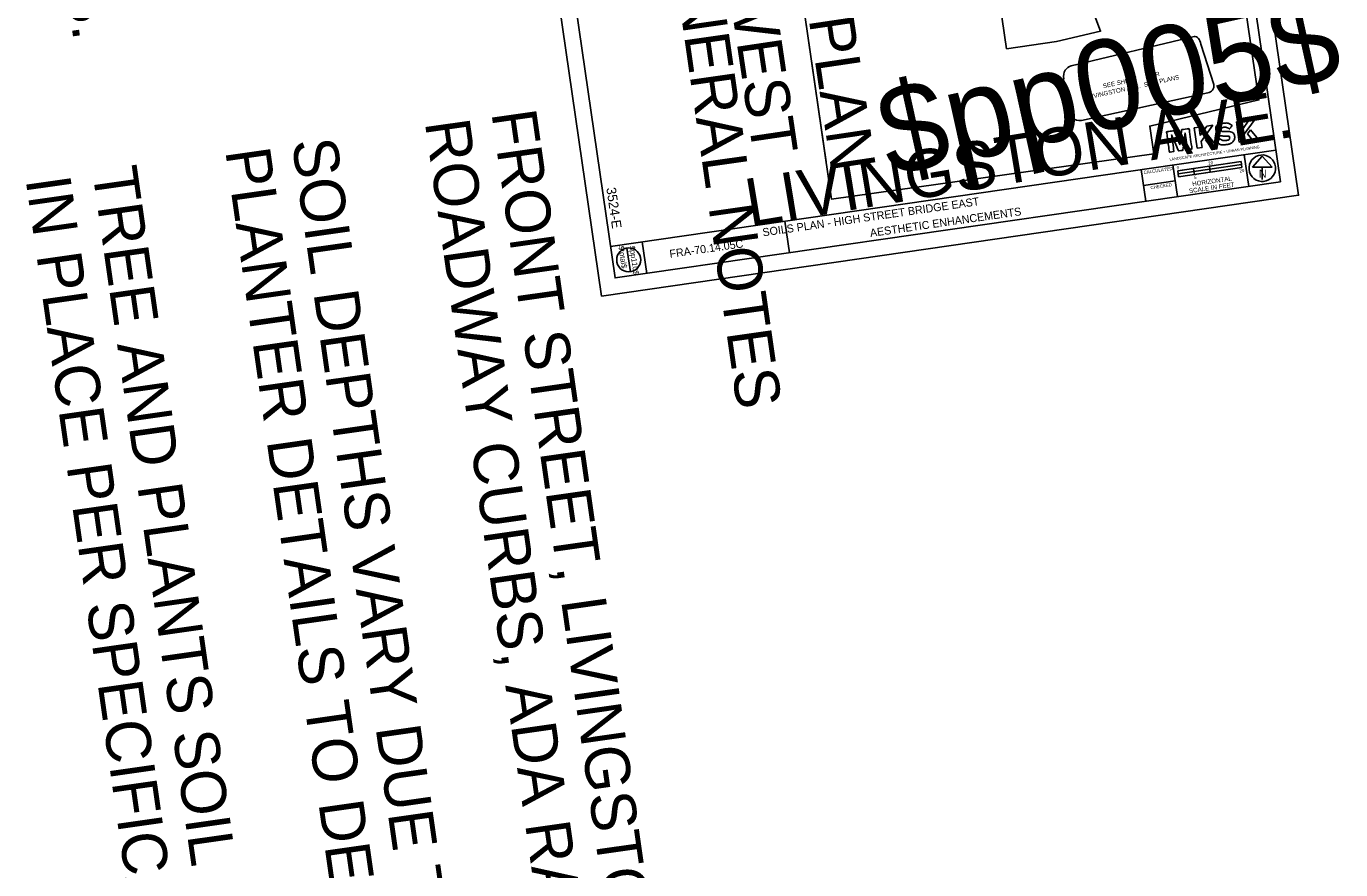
# Model space of a CAD drawing. Extents: x 1828401 to 1868248, y 433751 to 711935.
# Drawn here: x 1828401.1 to 1828811.8, y 711367.9 to 711631.6 of the extents above; entities that cross this region are included whole.
import ezdxf

# ---------------------------------------------------------------- set-up
doc = ezdxf.new("R2010")
doc.units = 0
for name, color, linetype in [('SC_Scratch1', 7, 'Continuous'), ('SC_Scratch2', 7, 'Continuous'), ('SH_Border', 7, 'Continuous'), ('SH_Cut_Line', 7, 'Continuous'), ('SH_Data', 7, 'Continuous'), ('SH_Text', 7, 'Continuous'), ('VG_P_Cells', 7, 'Continuous'), ('VG_P_Text', 7, 'Continuous')]:
    doc.layers.add(name, color=color, linetype=linetype)

# ---------------------------------------------------------------- blocks, each defined once
blk = doc.blocks.new('NARROW')
at = {"layer": 'SH_Data'}
for p, q in [((0, 0.374), (-0.308, 0.033)), ((-0.308, 0.033), (0.308, 0.033)), ((0.308, 0.033), (0, 0.374)), ((0, 0.033), (0, -0.354))]:
    blk.add_line(p, q, dxfattribs=at)
blk.add_arc((0, 0), 0.415, 129.7798, 129.7633, dxfattribs=at)
blk.add_text('N', height=0.25, rotation=360, dxfattribs=at).set_placement((-0.104, -0.291))

msp = doc.modelspace()

# ---------------------------------------------------------------- linework, layer by layer
at = {"layer": 'SC_Scratch1'}
msp.add_lwpolyline([(1828745.05, 711890.51), (1828786.22, 711608.59), (1828752.09, 711600.43), (1828753.34, 711591.74), (1828652.71, 711577.53), (1828610.22, 711870.99)], close=True, dxfattribs=at)
at = {"layer": 'SC_Scratch2'}
msp.add_lwpolyline([(1828707.37, 711624.58), (1828722.97, 711626.84), (1828736.77, 711630.05), (1828734.37, 711636.49), (1828732.45, 711641.74), (1828730.87, 711646.15), (1828729.12, 711651.11), (1828728.63, 711652.53), (1828703.84, 711648.94)], close=True, dxfattribs=at)
at = {"layer": 'SH_Border'}
for p, q in [((1828583.65, 711562.81), (1828791.49, 711592.9)), ((1828759.32, 711588.25), (1828760.76, 711578.35)), ((1828781.59, 711591.47), (1828783.02, 711581.57)), ((1828749.43, 711586.81), (1828750.86, 711576.92)), ((1828760.04, 711583.3), (1828750.14, 711581.86)), ((1828638.09, 711570.69), (1828639.52, 711560.8)), ((1828593.55, 711564.24), (1828594.98, 711554.35))]:
    msp.add_line(p, q, dxfattribs=at)
msp.add_lwpolyline([(1828747.79, 711894.75), (1828792.92, 711583.01), (1828585.09, 711552.92), (1828539.95, 711864.66)], close=True, dxfattribs=at)
at = {"layer": 'SH_Cut_Line'}
msp.add_lwpolyline([(1828532.14, 711883.74), (1828580.86, 711547.25), (1828798.59, 711578.77), (1828749.87, 711915.26)], close=True, dxfattribs=at)
at = {"layer": 'SH_Data'}
for p, q in [((1828760.85, 711586.44), (1828780.64, 711589.31)), ((1828770.74, 711587.88), (1828780.64, 711589.31)), ((1828780.78, 711588.38), (1828770.88, 711586.95)), ((1828780.91, 711587.45), (1828780.64, 711589.31)), ((1828780.64, 711589.31), (1828780.77, 711588.39)), ((1828780.77, 711588.39), (1828780.78, 711588.38)), ((1828765.8, 711587.16), (1828760.85, 711586.44)), ((1828761.12, 711584.59), (1828760.85, 711586.44)), ((1828760.85, 711586.44), (1828760.98, 711585.52)), ((1828760.98, 711585.52), (1828765.93, 711586.24)), ((1828780.91, 711587.45), (1828761.12, 711584.59)), ((1828765.93, 711586.24), (1828765.8, 711587.16)), ((1828770.88, 711586.95), (1828765.93, 711586.24)), ((1828765.93, 711586.24), (1828766.06, 711585.31)), ((1828766.06, 711585.31), (1828771.01, 711586.03)), ((1828770.88, 711586.95), (1828770.74, 711587.88)), ((1828771.01, 711586.03), (1828770.88, 711586.95)), ((1828787.26, 711587.24), (1828787.26, 711587.24)), ((1828787.26, 711587.24), (1828787.26, 711587.24)), ((1828588.78, 711562.29), (1828589.86, 711554.87))]:
    msp.add_line(p, q, dxfattribs=at)
msp.add_circle((1828589.32, 711558.58), 3.75, dxfattribs=at)
at = {"layer": 'SH_Text'}
for points in [[(1828727.6, 711619.22), (1828765.96, 711628.42)], [(1828768.08, 711626.07), (1828772.13, 711613.38)], [(1828726.25, 711605.67), (1828725.22, 711615.17)], [(1828770.21, 711610.79), (1828730.74, 711602.2)]]:
    msp.add_lwpolyline(points, dxfattribs=at)
for centre, major_axis, ratio, start_param, end_param in [((1828766.34, 711625.82), (-0.38, 2.6), 0.669934, 4.712389, 6.283185), ((1828728.13, 711615.59), (0.53, -3.63), 0.800334, 3.141593, 4.712389), ((1828769.88, 711613.06), (-0.33, 2.27), 0.993001, 3.141593, 4.712389), ((1828730.16, 711606.24), (0.59, -4.04), 0.966497, 4.712389, 6.283185)]:
    msp.add_ellipse(centre, major_axis=major_axis, ratio=ratio, start_param=start_param, end_param=end_param, dxfattribs=at)
at = {"layer": 'VG_P_Text'}
for p, q in [((1828610.22, 711870.99), (1828651.01, 711589.27)), ((1828769.92, 711600.41), (1828767.9, 711597.48)), ((1828768.17, 711595.57), (1828771.83, 711600.68)), ((1828771.83, 711600.68), (1828769.92, 711600.41)), ((1828780.7, 711601.93), (1828779.18, 711601.72)), ((1828779.18, 711601.72), (1828780.08, 711595.35)), ((1828781.07, 711599.34), (1828780.7, 711601.93)), ((1828783.08, 711602.27), (1828781.07, 711599.34)), ((1828781.34, 711597.43), (1828785, 711602.54)), ((1828785, 711602.54), (1828783.08, 711602.27)), ((1828767.54, 711600.08), (1828766.02, 711599.86)), ((1828766.02, 711599.86), (1828766.92, 711593.49)), ((1828767.9, 711597.48), (1828767.54, 711600.08)), ((1828770.42, 711597.37), (1828769.52, 711596.08)), ((1828772.91, 711594.34), (1828770.42, 711597.37)), ((1828781.6, 711595.56), (1828781.34, 711597.43)), ((1828783.59, 711599.23), (1828782.68, 711597.94)), ((1828782.68, 711597.94), (1828784.28, 711595.94)), ((1828786.08, 711596.2), (1828783.59, 711599.23)), ((1828784.28, 711595.94), (1828786.08, 711596.2)), ((1828766.92, 711593.49), (1828768.44, 711593.7)), ((1828768.44, 711593.7), (1828768.17, 711595.57)), ((1828769.52, 711596.08), (1828771.12, 711594.08)), ((1828771.12, 711594.08), (1828772.91, 711594.34)), ((1828780.08, 711595.35), (1828781.6, 711595.56))]:
    msp.add_line(p, q, dxfattribs=at)
for points in [[(1828777.31, 711598.66), (1828776.93, 711598.73), (1828775.99, 711598.78), (1828775.3, 711598.76), (1828775.03, 711598.76), (1828774.48, 711598.75), (1828774.41, 711599.24), (1828774.36, 711599.55), (1828774.63, 711599.95), (1828775.26, 711600.04), (1828775.67, 711600.1), (1828776.09, 711600), (1828776.34, 711599.91), (1828776.61, 711599.8), (1828776.82, 711599.66), (1828777.04, 711599.49), (1828777.04, 711599.49), (1828777.87, 711600.64), (1828777.87, 711600.64), (1828777.26, 711601.04), (1828776.41, 711601.48), (1828775.11, 711601.3), (1828774.01, 711601.15), (1828772.62, 711600.45), (1828772.85, 711598.81), (1828773.04, 711597.44), (1828774.41, 711597.35), (1828774.81, 711597.32), (1828775.16, 711597.3), (1828775.52, 711597.3), (1828775.88, 711597.3), (1828776.36, 711597.31), (1828777.01, 711597.32), (1828777.08, 711596.81), (1828777.14, 711596.37), (1828776.64, 711596), (1828776.01, 711595.91), (1828775.64, 711595.85), (1828775.2, 711595.87), (1828774.74, 711596.04), (1828774.4, 711596.17), (1828774.25, 711596.29), (1828774.06, 711596.45), (1828774.06, 711596.45), (1828773.22, 711595.29), (1828773.22, 711595.29), (1828773.72, 711594.89), (1828774.55, 711594.42), (1828776.04, 711594.63), (1828776.94, 711594.76), (1828777.83, 711595.08), (1828778.31, 711595.83), (1828778.59, 711596.26), (1828778.69, 711596.79), (1828778.63, 711597.25), (1828778.53, 711597.97), (1828778.08, 711598.49), (1828777.31, 711598.66)], [(1828777.31, 711598.66), (1828776.93, 711598.73), (1828775.99, 711598.78), (1828775.3, 711598.76), (1828775.03, 711598.76), (1828774.48, 711598.75), (1828774.41, 711599.24), (1828774.36, 711599.55), (1828774.63, 711599.95), (1828775.26, 711600.04), (1828775.67, 711600.1), (1828776.09, 711600), (1828776.34, 711599.91), (1828776.61, 711599.8), (1828776.82, 711599.66), (1828777.04, 711599.49), (1828777.04, 711599.49), (1828777.87, 711600.64), (1828777.87, 711600.64), (1828777.26, 711601.04), (1828776.41, 711601.48), (1828775.11, 711601.3), (1828774.01, 711601.15), (1828772.62, 711600.45), (1828772.85, 711598.81), (1828773.04, 711597.44), (1828774.41, 711597.35), (1828774.81, 711597.32), (1828775.16, 711597.3), (1828775.52, 711597.3), (1828775.88, 711597.3), (1828776.36, 711597.31), (1828777.01, 711597.32), (1828777.08, 711596.81), (1828777.14, 711596.37), (1828776.64, 711596), (1828776.01, 711595.91), (1828775.64, 711595.85), (1828775.2, 711595.87), (1828774.74, 711596.04), (1828774.4, 711596.17), (1828774.25, 711596.29), (1828774.06, 711596.45), (1828774.06, 711596.45), (1828773.22, 711595.29), (1828773.22, 711595.29), (1828773.72, 711594.89), (1828774.55, 711594.42), (1828776.04, 711594.63), (1828776.94, 711594.76), (1828777.83, 711595.08), (1828778.31, 711595.83), (1828778.59, 711596.26), (1828778.69, 711596.79), (1828778.63, 711597.25), (1828778.53, 711597.97), (1828778.08, 711598.49), (1828777.31, 711598.66)], [(1828764.41, 711599.63), (1828764.41, 711599.63), (1828765.31, 711593.26), (1828765.31, 711593.26), (1828765.31, 711593.26), (1828763.9, 711593.06), (1828763.9, 711593.06), (1828763.9, 711593.06), (1828763.26, 711597.6), (1828763.26, 711597.6), (1828763.26, 711597.6), (1828763.17, 711598.24), (1828763.17, 711598.24), (1828763.17, 711598.24), (1828763.14, 711598.01), (1828763.14, 711598.01), (1828763.11, 711597.64), (1828763.11, 711597.59), (1828763.08, 711597.31), (1828763.08, 711597.31), (1828762.48, 711592.86), (1828762.48, 711592.86), (1828762.48, 711592.86), (1828761.11, 711592.67), (1828761.11, 711592.67), (1828761.11, 711592.67), (1828759.38, 711596.6), (1828759.38, 711596.6), (1828759.38, 711596.6), (1828758.94, 711597.7), (1828758.94, 711597.7), (1828759.01, 711597.2), (1828759.03, 711597.09), (1828759.11, 711596.48), (1828759.11, 711596.48), (1828759.68, 711592.47), (1828759.68, 711592.47), (1828759.68, 711592.47), (1828758.27, 711592.27), (1828758.27, 711592.27), (1828758.27, 711592.27), (1828757.37, 711598.64), (1828757.37, 711598.64), (1828757.37, 711598.64), (1828759.7, 711598.97), (1828759.7, 711598.97), (1828759.7, 711598.97), (1828761.17, 711595.53), (1828761.17, 711595.53), (1828761.17, 711595.53), (1828761.54, 711594.54), (1828761.54, 711594.54), (1828761.57, 711595), (1828761.57, 711595.05), (1828761.6, 711595.35), (1828761.6, 711595.35), (1828762.09, 711599.31), (1828762.09, 711599.31), (1828762.09, 711599.31), (1828764.41, 711599.63), (1828764.41, 711599.63)], [(1828764.41, 711599.63), (1828764.41, 711599.63), (1828765.31, 711593.26), (1828765.31, 711593.26), (1828765.31, 711593.26), (1828763.9, 711593.06), (1828763.9, 711593.06), (1828763.9, 711593.06), (1828763.26, 711597.6), (1828763.26, 711597.6), (1828763.26, 711597.6), (1828763.17, 711598.24), (1828763.17, 711598.24), (1828763.17, 711598.24), (1828763.14, 711598.01), (1828763.14, 711598.01), (1828763.11, 711597.64), (1828763.11, 711597.59), (1828763.08, 711597.31), (1828763.08, 711597.31), (1828762.48, 711592.86), (1828762.48, 711592.86), (1828762.48, 711592.86), (1828761.11, 711592.67), (1828761.11, 711592.67), (1828761.11, 711592.67), (1828759.38, 711596.6), (1828759.38, 711596.6), (1828759.38, 711596.6), (1828758.94, 711597.7), (1828758.94, 711597.7), (1828759.01, 711597.2), (1828759.03, 711597.09), (1828759.11, 711596.48), (1828759.11, 711596.48), (1828759.68, 711592.47), (1828759.68, 711592.47), (1828759.68, 711592.47), (1828758.27, 711592.27), (1828758.27, 711592.27), (1828758.27, 711592.27), (1828757.37, 711598.64), (1828757.37, 711598.64), (1828757.37, 711598.64), (1828759.7, 711598.97), (1828759.7, 711598.97), (1828759.7, 711598.97), (1828761.17, 711595.53), (1828761.17, 711595.53), (1828761.17, 711595.53), (1828761.54, 711594.54), (1828761.54, 711594.54), (1828761.57, 711595), (1828761.57, 711595.05), (1828761.6, 711595.35), (1828761.6, 711595.35), (1828762.09, 711599.31), (1828762.09, 711599.31), (1828762.09, 711599.31), (1828764.41, 711599.63), (1828764.41, 711599.63)]]:
    msp.add_open_spline(points, degree=3, dxfattribs=at)

# ---------------------------------------------------------------- block references
at = {"layer": 'SH_Border', "xscale": 10.000000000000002, "yscale": 10, "rotation": 0.22807231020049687}
msp.add_blockref('NARROW', (1828787.26, 711587.24), dxfattribs=at)

# ---------------------------------------------------------------- texts
at = {"layer": 'SH_Data'}
for s, height, rotation, p in [('10', 1, 8.238, (1828770.45, 711588.3)), ('CALCULATED', 1, 8.238, (1828750.28, 711585.4)), ('0', 1, 8.238, (1828760.6, 711586.88)), ('HORIZONTAL', 1.4, 8.238, (1828765.49, 711581.61)), ('5', 1, 8.238, (1828766.03, 711583.82)), ('20', 1, 8.238, (1828780.21, 711585.88)), ('CHECKED', 1, 8.238, (1828752.42, 711580.65)), ('SCALE IN FEET', 1.4, 8.238, (1828764.5, 711579.45)), ('          SOILS PLAN - HIGH STREET BRIDGE EAST', 2.5, 8.238, (1828622.13, 711564.59)), ('AESTHETIC ENHANCEMENTS', 2.5, 8.238, (1828664.88, 711565.73)), ('FRA-70.14.05C', 2.5, 8.238, (1828602.26, 711559.19)), ('$total$', 1.7, 278.238, (1828586.13, 711562.84)), ('$pp110$', 1.7, 278.238, (1828589.55, 711562.89))]:
    msp.add_text(s, height=height, rotation=rotation, dxfattribs=at).set_placement(p)
at = {"layer": 'SH_Text'}
for s, height, rotation, p in [('$pp005$', 28, 12.468, (1828671.03, 711584.14)), ('SEE SHEET      FOR ', 1.4, 12.468, (1828737.62, 711612.21)), ('LIVINGSTON AVE.  SOIL PLANS', 1.4, 12.468, (1828733.12, 711608.82)), ('LIVINGSTON AVE.', 15, 9.43, (1828627.18, 711568.86))]:
    msp.add_text(s, height=height, rotation=rotation, dxfattribs=at).set_placement(p)
at = {"layer": 'VG_P_Cells'}
msp.add_text('3524-E', height=3, rotation=278.238, dxfattribs=at).set_placement((1828582.33, 711581.02))
at = {"layer": 'VG_P_Text'}
for s, height, rotation, p in [('REFER TO SHEET       FOR SOILS PLAN', 14, 278.466, (1828600.83, 711934.34)), ('OF HIGH STREET BRIDGE WEST', 14, 278.466, (1828585.2, 711880.87)), ('GENERAL NOTES', 14, 278.1248, (1828600.86, 711668.95)), ('3.', 14, 278.1248, (1828413.75, 711642.23)), ('FRONT STREET, LIVINGSTON AVENUE) FOR CONSTRUCTION OF VEHICULAR PAVEMENT,', 14, 278.1248, (1828546.4, 711604.6)), ('ROADWAY CURBS, ADA RAMPS AND CROSSWALKS.', 14, 278.1248, (1828525.61, 711601.64)), ('PLANTER DETAILS TO DETERMINE SOIL DEPTHS OF INDIVIDUAL PLANTERS.', 14, 278.1248, (1828463.25, 711592.73)), ('SOIL DEPTHS VARY DUE TO PRECAST PLANTER HEIGHTS. REFER TO PRECAST', 14, 278.1248, (1828484.04, 711595.7)), ('LANDSCAPE ARCHITECTURE + URBAN PLANNING', 0.85, 8.0365, (1828758.36, 711589.55)), ('TREE AND PLANTS SOIL MIX TO BE INSTALLED IN MAX. 8" LIFTS AND COMPACTED', 14, 278.1248, (1828421.67, 711586.8)), ('IN PLACE PER SPECIFICATIONS TO FILL THE VOLUME INSIDE THE PLANTERS.', 14, 278.1248, (1828400.88, 711583.83))]:
    msp.add_text(s, height=height, rotation=rotation, dxfattribs=at).set_placement(p)

doc.saveas('drawing.dxf')
